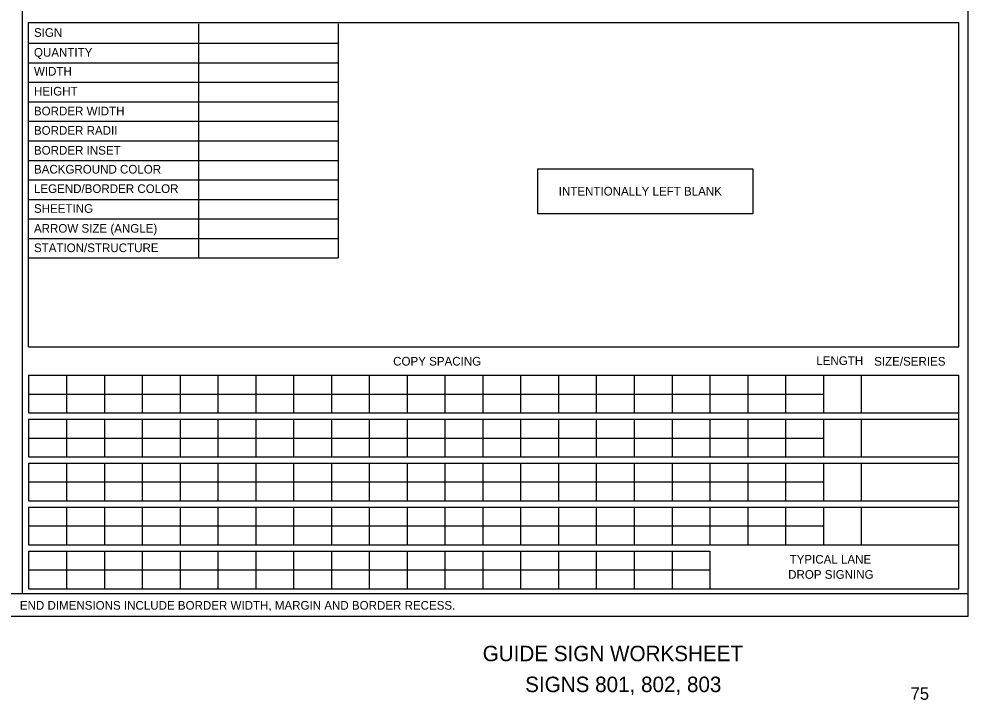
# Model space of a CAD drawing. Extents: x 10268147 to 10268469, y 2141099 to 2141204.
# Drawn here: x 10268229.5 to 10268306.3, y 2141101.8 to 2141156.9 of the extents above; entities that cross this region are included whole.
import ezdxf

# ---------------------------------------------------------------- set-up
doc = ezdxf.new("R2010")
doc.units = 0
for name, color, linetype in [('61', 7, 'Continuous'), ('Miscellaneous0', 7, 'Continuous'), ('SheetLinesMisc2_dp', 7, 'Continuous'), ('TextMisc', 7, 'Continuous'), ('TextNotes', 7, 'Continuous'), ('TextShtNo', 7, 'Continuous')]:
    doc.layers.add(name, color=color, linetype=linetype)

msp = doc.modelspace()

# ---------------------------------------------------------------- linework, layer by layer
at = {"layer": '61'}
for p, q in [((10268230.252, 2141130.401), (10268230.252, 2141156.65)), ((10268230.252, 2141156.65), (10268305.587, 2141156.65)), ((10268244.007, 2141156.541), (10268244.007, 2141137.584)), ((10268255.325, 2141156.541), (10268255.325, 2141137.584)), ((10268305.587, 2141130.401), (10268305.587, 2141156.65)), ((10268230.252, 2141154.961), (10268255.325, 2141154.961)), ((10268230.252, 2141153.382), (10268255.325, 2141153.382)), ((10268230.252, 2141151.802), (10268255.325, 2141151.802)), ((10268230.252, 2141150.222), (10268255.325, 2141150.222)), ((10268230.252, 2141148.642), (10268255.325, 2141148.642)), ((10268230.252, 2141147.062), (10268255.325, 2141147.062)), ((10268230.252, 2141145.483), (10268255.325, 2141145.483)), ((10268230.252, 2141143.903), (10268255.325, 2141143.903)), ((10268230.252, 2141142.323), (10268255.325, 2141142.323)), ((10268230.252, 2141140.743), (10268255.325, 2141140.743)), ((10268230.252, 2141139.164), (10268255.325, 2141139.164)), ((10268230.252, 2141137.584), (10268255.325, 2141137.584)), ((10268230.252, 2141130.401), (10268305.587, 2141130.401)), ((10268230.252, 2141128.106), (10268305.587, 2141128.106)), ((10268230.252, 2141128.106), (10268230.252, 2141125.046)), ((10268233.317, 2141128.106), (10268233.317, 2141125.046)), ((10268236.382, 2141128.106), (10268236.382, 2141125.046)), ((10268239.446, 2141128.106), (10268239.446, 2141125.046)), ((10268242.51, 2141128.106), (10268242.51, 2141125.046)), ((10268245.575, 2141128.106), (10268245.575, 2141125.046)), ((10268248.64, 2141128.106), (10268248.64, 2141125.046)), ((10268251.704, 2141128.106), (10268251.704, 2141125.046)), ((10268254.769, 2141128.106), (10268254.769, 2141125.046)), ((10268257.833, 2141128.106), (10268257.833, 2141125.046)), ((10268260.898, 2141128.106), (10268260.898, 2141125.046)), ((10268263.963, 2141128.106), (10268263.963, 2141125.046)), ((10268267.027, 2141128.106), (10268267.027, 2141125.046)), ((10268270.091, 2141128.106), (10268270.091, 2141125.046)), ((10268273.157, 2141128.106), (10268273.157, 2141125.046)), ((10268276.221, 2141128.106), (10268276.221, 2141125.046)), ((10268279.285, 2141128.106), (10268279.285, 2141125.046)), ((10268282.35, 2141128.106), (10268282.35, 2141125.046)), ((10268285.415, 2141128.106), (10268285.415, 2141125.046)), ((10268288.479, 2141128.106), (10268288.479, 2141125.046)), ((10268291.544, 2141128.106), (10268291.544, 2141125.046)), ((10268294.609, 2141128.106), (10268294.609, 2141125.046)), ((10268297.673, 2141128.106), (10268297.673, 2141125.046)), ((10268305.587, 2141110.808), (10268305.587, 2141128.106)), ((10268230.252, 2141126.576), (10268294.609, 2141126.576)), ((10268230.252, 2141125.046), (10268305.587, 2141125.046)), ((10268230.252, 2141124.547), (10268305.587, 2141124.547)), ((10268230.252, 2141124.547), (10268230.252, 2141121.487)), ((10268233.317, 2141124.547), (10268233.317, 2141121.487)), ((10268236.382, 2141124.547), (10268236.382, 2141121.487)), ((10268239.446, 2141124.547), (10268239.446, 2141121.487)), ((10268242.51, 2141124.547), (10268242.51, 2141121.487)), ((10268245.575, 2141124.547), (10268245.575, 2141121.487)), ((10268248.64, 2141124.547), (10268248.64, 2141121.487)), ((10268251.704, 2141124.547), (10268251.704, 2141121.487)), ((10268254.769, 2141124.547), (10268254.769, 2141121.487)), ((10268257.833, 2141124.547), (10268257.833, 2141121.487)), ((10268260.898, 2141124.547), (10268260.898, 2141121.487)), ((10268263.963, 2141124.547), (10268263.963, 2141121.487)), ((10268267.027, 2141124.547), (10268267.027, 2141121.487)), ((10268270.091, 2141124.547), (10268270.091, 2141121.487)), ((10268273.157, 2141124.547), (10268273.157, 2141121.487)), ((10268276.221, 2141124.547), (10268276.221, 2141121.487)), ((10268279.285, 2141124.547), (10268279.285, 2141121.487)), ((10268282.35, 2141124.547), (10268282.35, 2141121.487)), ((10268285.415, 2141124.547), (10268285.415, 2141121.487)), ((10268288.479, 2141124.547), (10268288.479, 2141121.487)), ((10268291.544, 2141124.547), (10268291.544, 2141121.487)), ((10268294.609, 2141124.547), (10268294.609, 2141121.487)), ((10268297.673, 2141124.547), (10268297.673, 2141121.487)), ((10268230.252, 2141123.016), (10268294.609, 2141123.016)), ((10268230.252, 2141121.487), (10268305.587, 2141121.487)), ((10268230.252, 2141120.988), (10268305.587, 2141120.988)), ((10268230.252, 2141120.988), (10268230.252, 2141117.927)), ((10268233.317, 2141120.988), (10268233.317, 2141117.927)), ((10268236.382, 2141120.988), (10268236.382, 2141117.927)), ((10268239.446, 2141120.988), (10268239.446, 2141117.927)), ((10268242.51, 2141120.988), (10268242.51, 2141117.927)), ((10268245.575, 2141120.988), (10268245.575, 2141117.927)), ((10268248.64, 2141120.988), (10268248.64, 2141117.927)), ((10268251.704, 2141120.988), (10268251.704, 2141117.927)), ((10268254.769, 2141120.988), (10268254.769, 2141117.927)), ((10268257.833, 2141120.988), (10268257.833, 2141117.927)), ((10268260.898, 2141120.988), (10268260.898, 2141117.927)), ((10268263.963, 2141120.988), (10268263.963, 2141117.927)), ((10268267.027, 2141120.988), (10268267.027, 2141117.927)), ((10268270.091, 2141120.988), (10268270.091, 2141117.927)), ((10268273.157, 2141120.988), (10268273.157, 2141117.927)), ((10268276.221, 2141120.988), (10268276.221, 2141117.927)), ((10268279.285, 2141120.988), (10268279.285, 2141117.927)), ((10268282.35, 2141120.988), (10268282.35, 2141117.927)), ((10268285.415, 2141120.988), (10268285.415, 2141117.927)), ((10268288.479, 2141120.988), (10268288.479, 2141117.927)), ((10268291.544, 2141120.988), (10268291.544, 2141117.927)), ((10268294.609, 2141120.988), (10268294.609, 2141117.927)), ((10268297.673, 2141120.988), (10268297.673, 2141117.927)), ((10268230.252, 2141119.457), (10268294.609, 2141119.457)), ((10268230.252, 2141117.927), (10268305.587, 2141117.927)), ((10268230.252, 2141117.428), (10268305.587, 2141117.428)), ((10268230.252, 2141117.428), (10268230.252, 2141114.367)), ((10268233.317, 2141117.428), (10268233.317, 2141114.367)), ((10268236.382, 2141117.428), (10268236.382, 2141114.367)), ((10268239.446, 2141117.428), (10268239.446, 2141114.367)), ((10268242.51, 2141117.428), (10268242.51, 2141114.367)), ((10268245.575, 2141117.428), (10268245.575, 2141114.367)), ((10268248.64, 2141117.428), (10268248.64, 2141114.367)), ((10268251.704, 2141117.428), (10268251.704, 2141114.367)), ((10268254.769, 2141117.428), (10268254.769, 2141114.367)), ((10268257.833, 2141117.428), (10268257.833, 2141114.367)), ((10268260.898, 2141117.428), (10268260.898, 2141114.367)), ((10268263.963, 2141117.428), (10268263.963, 2141114.367)), ((10268267.027, 2141117.428), (10268267.027, 2141114.367)), ((10268270.091, 2141117.428), (10268270.091, 2141114.367)), ((10268273.157, 2141117.428), (10268273.157, 2141114.367)), ((10268276.221, 2141117.428), (10268276.221, 2141114.367)), ((10268279.285, 2141117.428), (10268279.285, 2141114.367)), ((10268282.35, 2141117.428), (10268282.35, 2141114.367)), ((10268285.415, 2141117.428), (10268285.415, 2141114.367)), ((10268288.479, 2141117.428), (10268288.479, 2141114.367)), ((10268291.544, 2141117.428), (10268291.544, 2141114.367)), ((10268294.609, 2141117.428), (10268294.609, 2141114.367)), ((10268297.673, 2141117.428), (10268297.673, 2141114.367)), ((10268230.252, 2141115.898), (10268294.609, 2141115.898)), ((10268230.252, 2141114.367), (10268305.587, 2141114.367)), ((10268230.252, 2141113.868), (10268230.252, 2141110.808)), ((10268230.252, 2141113.868), (10268285.415, 2141113.868)), ((10268233.317, 2141113.868), (10268233.317, 2141110.808)), ((10268236.382, 2141113.868), (10268236.382, 2141110.808)), ((10268239.446, 2141113.868), (10268239.446, 2141110.808)), ((10268242.51, 2141113.868), (10268242.51, 2141110.808)), ((10268245.575, 2141113.868), (10268245.575, 2141110.808)), ((10268248.64, 2141113.868), (10268248.64, 2141110.808)), ((10268251.704, 2141113.868), (10268251.704, 2141110.808)), ((10268254.769, 2141113.868), (10268254.769, 2141110.808)), ((10268257.833, 2141113.868), (10268257.833, 2141110.808)), ((10268260.898, 2141113.868), (10268260.898, 2141110.808)), ((10268263.963, 2141113.868), (10268263.963, 2141110.808)), ((10268267.027, 2141113.868), (10268267.027, 2141110.808)), ((10268270.091, 2141113.868), (10268270.091, 2141110.808)), ((10268273.157, 2141113.868), (10268273.157, 2141110.808)), ((10268276.221, 2141113.868), (10268276.221, 2141110.808)), ((10268279.285, 2141113.868), (10268279.285, 2141110.808)), ((10268282.35, 2141113.868), (10268282.35, 2141110.808)), ((10268285.415, 2141113.868), (10268285.415, 2141110.808)), ((10268230.252, 2141112.338), (10268285.415, 2141112.338)), ((10268230.252, 2141110.808), (10268305.587, 2141110.808))]:
    msp.add_line(p, q, dxfattribs=at)
at = {"layer": 'Miscellaneous0'}
msp.add_lwpolyline([(10268271.498, 2141144.805), (10268288.891, 2141144.805), (10268288.891, 2141141.149), (10268271.498, 2141141.149)], close=True, dxfattribs=at)
at = {"layer": 'SheetLinesMisc2_dp'}
for p, q in [((10268229.73, 2141203.955), (10268229.73, 2141110.434)), ((10268306.32, 2141108.602), (10268306.32, 2141203.954)), ((10268153.14, 2141110.434), (10268306.32, 2141110.434)), ((10268153.14, 2141108.602), (10268306.32, 2141108.602))]:
    msp.add_line(p, q, dxfattribs=at)

# ---------------------------------------------------------------- texts
at = {"layer": 'Miscellaneous0'}
msp.add_text('INTENTIONALLY LEFT BLANK', height=0.7, dxfattribs=at).set_placement((10268273.179, 2141142.638))
at = {"layer": 'TextMisc'}
for s, p in [('SIGN', (10268230.682, 2141155.478)), ('QUANTITY', (10268230.682, 2141153.87)), ('WIDTH', (10268230.682, 2141152.339)), ('HEIGHT', (10268230.682, 2141150.731)), ('BORDER WIDTH', (10268230.682, 2141149.123)), ('BORDER RADII', (10268230.682, 2141147.554)), ('BORDER INSET', (10268230.682, 2141145.945)), ('BACKGROUND COLOR', (10268230.682, 2141144.414)), ('LEGEND/BORDER COLOR', (10268230.682, 2141142.845)), ('SHEETING', (10268230.682, 2141141.237)), ('ARROW SIZE (ANGLE)', (10268230.682, 2141139.629)), ('STATION/STRUCTURE', (10268230.682, 2141138.059)), ('COPY SPACING', (10268259.769, 2141128.879)), ('LENGTH', (10268294.033, 2141128.926)), ('SIZE/SERIES', (10268298.721, 2141128.87))]:
    msp.add_text(s, height=0.7, dxfattribs=at).set_placement(p)
for s, p in [('  GUIDE SIGN WORKSHEET  ', (10268266.091, 2141104.955)), ('  SIGNS 801, 802, 803   ', (10268269.53, 2141102.455))]:
    msp.add_text(s, height=1.25, rotation=360, dxfattribs=at).set_placement(p)
at = {"layer": 'TextNotes'}
for s, p in [('TYPICAL LANE', (10268291.873, 2141112.85)), ('DROP SIGNING', (10268291.754, 2141111.625)), ('NOTES:          WIDTH - HORIZONTAL SPACING DIMENSIONS ARE IN INCHES.          END DIMENSIONS INCLUDE BORDER WIDTH, MARGIN AND BORDER RECESS.  ', (10268192.823, 2141109.124))]:
    msp.add_text(s, height=0.7, dxfattribs=at).set_placement(p)
at = {"layer": 'TextShtNo'}
msp.add_text('  75  ', height=1, rotation=360, dxfattribs=at).set_placement((10268300.93, 2141101.83))

doc.saveas('drawing.dxf')
